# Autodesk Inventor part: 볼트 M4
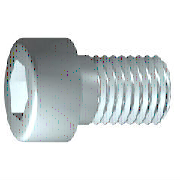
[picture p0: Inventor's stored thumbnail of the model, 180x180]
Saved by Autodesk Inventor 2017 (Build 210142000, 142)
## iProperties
IsCustomPart: 0
Created: 2012-02
Part Number: 볼트 M4
Material: 스테인리스강
Description: 6각 소켓 머리 캡 나사
Document SubType Name: Modeling
Standard: ISO 4762
Designer: mduedu
Standard Revision: Fourth edition 2004-03-01
Standards Organization: ISO
Language: ko-KR
Size Designation: M4 x 12
Categories: <MemberInstance><Categories><Category DisplayName="조임쇠" InternalName="e4da775c-781d-43d5-af7c-5136215cf5a6" Mnemonic="FSTN"><Category DisplayName="볼트" InternalN
Density: 8.08 g/cm^3
Mass: 2.29719 g
Surface Area: 3.30853 cm^2
Volume: 0.284306 cm^3
Appearance: 반광택
Author: mduedu
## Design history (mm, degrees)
sketch "스케치1"
  geometry: L1 (-1, 0)-(12, 0); L2 (12, 0)-(12, 2); L3 (12, 2)-(1.75, 2); L4 (1.75, 2)-(1.32, 2); L5 (1.32, 2)-(0, 2); L6 (0, 2)-(0, 3.5); L7 (0, 3.5)-(-4, 3.5); L8 (-4, 3.5)-(-4, 1.732); L9 (-4, 1.732)-(-2, 1.732); L10 (-2, 1.732)-(-1, 0); L11 (-7.2, 0)-(15.2, 0) reference; L12 (0, -0.7)-(0, 4.2) reference; L13 (1.75, 2)-(0, 2)
  constraints: 22 end point, 6 parallel, 2 collinear, 2 perpendicular, 1 horizontal, 1 point on line
  dimensions: "d1" = 10.25 distance from line of L3.end L2 (= GEL); "d2" = 0.42952 distance of L4.end L3.end (computed from GAL); "d3" = 4 distance between parallel lines of L8 L6 (= KOH); "d4" = 2 distance of L8.end L9.end (= INTI); "d5" = 60 deg angle of L10 L1; "d6" = 4 diameter of L3 L1 (= GD); "d7" = 4 diameter of L5 L1 (= BDM); "d8" = 3.4641 diameter of L9 L1 (= 1.1547 x SW); "d9" = 7 diameter of L7 L1 (= KOD); "d26" = 12 distance between parallel lines of L12 L2 (= NLG)
revolve "본체" sketch "스케치1" stored, may be unused: angle "d10" = 90 deg
sketch "스케치2"
  geometry: L1 (0, -4.9)-(0, 4.9) reference; L2 (-4.9, 0)-(4.9, 0) reference; L3 (1.732, 0)-(0.866, -1.5); L4 (0.866, -1.5)-(-0.866, -1.5); L5 (-0.866, -1.5)-(-1.732, 0); L6 (-1.732, 0)-(-0.866, 1.5); L7 (-0.866, 1.5)-(0.866, 1.5); L8 (0.866, 1.5)-(1.732, 0); 2 further points
  constraints: 12 end point, 1 coincident, 1 horizontal alignment, 1 point on line, 12 other
extrude "슬롯" join sketch "스케치2" stored distance "d11" = 10; taper "d12" = 0 deg
workplane "Work Plane1"
fillet "Fillet2" dims "d30" = 0.1 (= R)
body "Solid1"
fillet "모깎기1" dims "d17" = 0.4 (= RR)
feature "스레드" dims "d13" = 10.25 (= GEL), "d14" = 0
chamfer "모따기1" distance "d15" = 0.42941 (= -0.5 x SPD + 0.5 x GD); stored, may be unused: second distance "d16" = 0.42941 (= GUL), angle "d27" = 45 deg
other parameters: "GD" = 4 [user parameter; used in 2 equation terms], "NLG" = 12 [user parameter; used in 1 equation term], "GEL" = 10.25 [user parameter; used in 2 equation terms], "KOD" = 7 [user parameter; used in 1 equation term], "KOH" = 4 [user parameter; used in 1 equation term], "INTI" = 2 [user parameter; used in 1 equation term], "GAL" = 0.42941 (= 0.61345 x PTC) [user parameter; used in 1 equation term], "GUL" = 0.42941 (= 0.61345 x PTC) [user parameter; used in 1 equation term], "BDM" = 4 (= NND) [user parameter; used in 1 equation term], "SW" = 3 [user parameter; used in 2 equation terms], "RR" = 0.4 [user parameter; used in 1 equation term], "SPD" = 3.14117 (= NND - 1.2269 x PTC) [user parameter; used in 1 equation term], "d19" = 0, "d28" = 0, "d29" = 0, "R" = 0.1 [user parameter; used in 1 equation term], "TOA" = 30 deg [user parameter], "GD1" = 3.14117 (= THREADDIA - 1.2269 x PTC) [user parameter], "THREADDIA" = 4 [user parameter; used in 1 equation term], "FAWI" = 45 deg [user parameter], "TPU" = 14.28571 (computed from PTC) [user parameter], "PTC" = 0.7 [user parameter; used in 5 equation terms], "NND" = 4 [user parameter; used in 2 equation terms], "E0" = 3.465 (= 1.155 x SW) [user parameter]
